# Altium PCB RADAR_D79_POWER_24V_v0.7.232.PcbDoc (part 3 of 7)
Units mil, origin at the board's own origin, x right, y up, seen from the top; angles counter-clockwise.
Board outline 3110.24 x 3110.24 mil, 8 copper layers (Top Layer, GND1, SIG1, PWR1, PWR2, SIG2, GND2, Bottom Layer), stack 55.2 mil thick; 304 components, 269 nets, 1408 pads, 1367 vias.
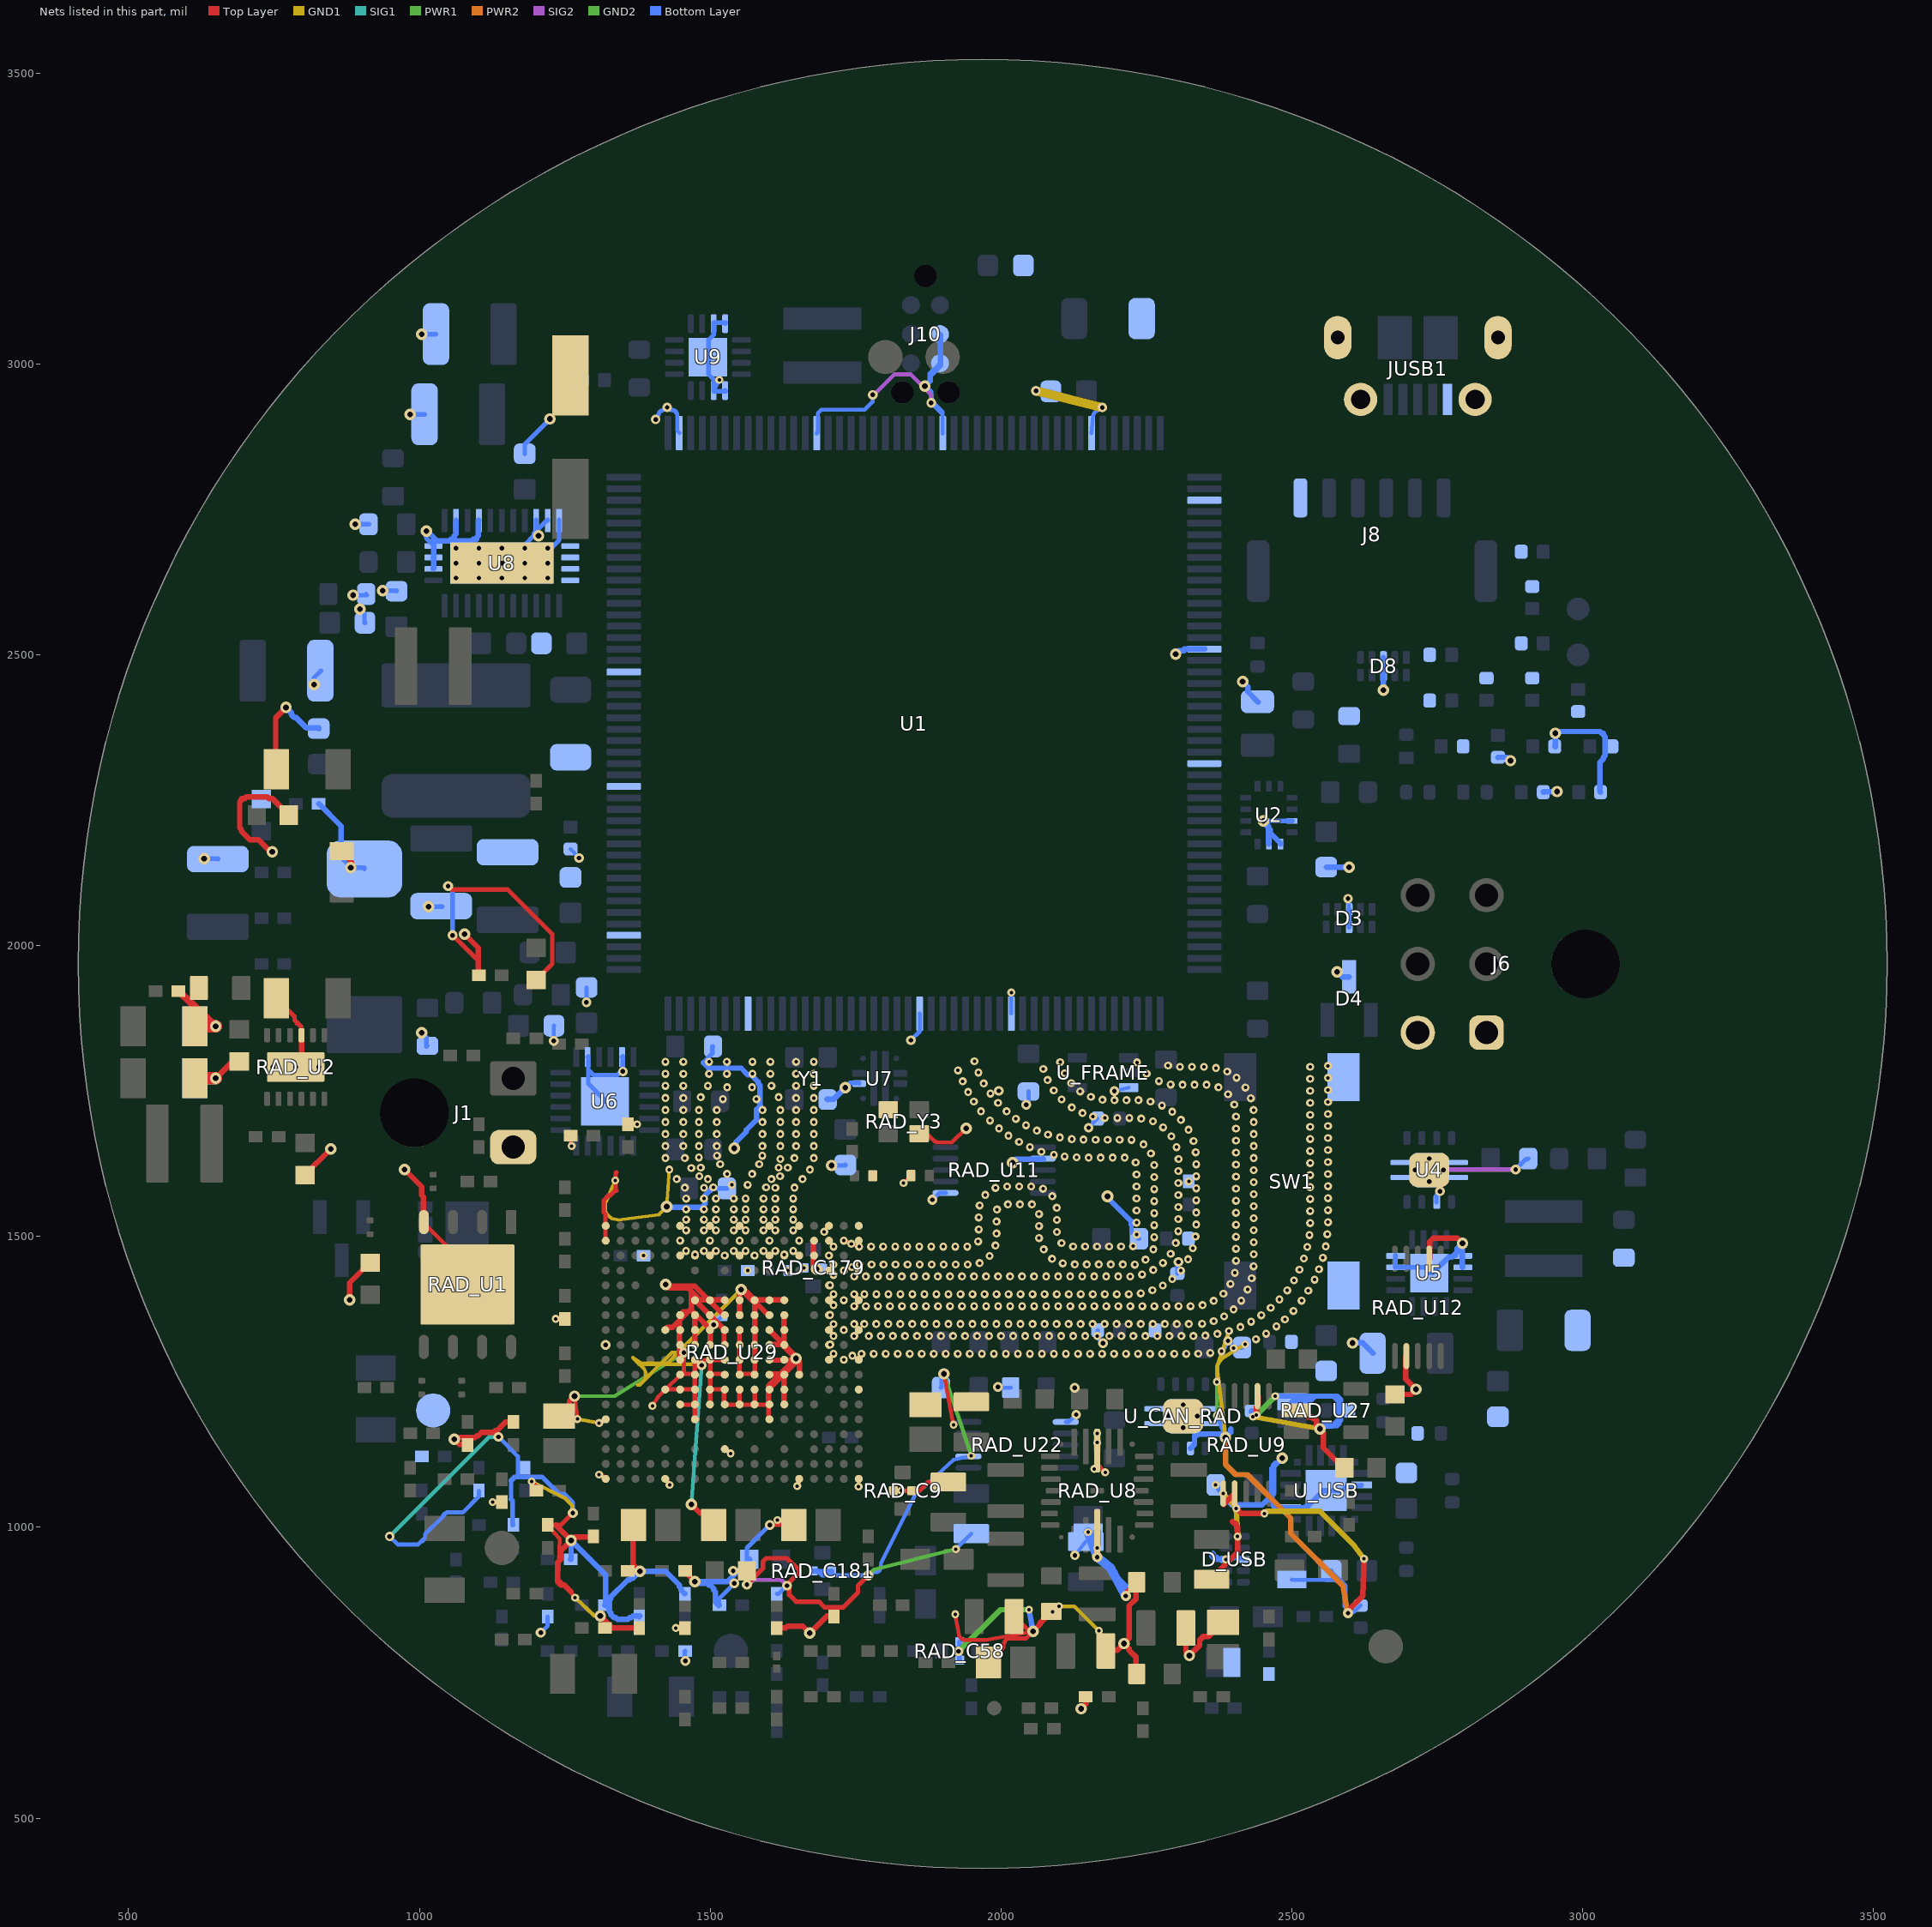
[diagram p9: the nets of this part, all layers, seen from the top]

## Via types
v1: diameter 13.77, hole 5.9, Top Layer to GND1, tented both sides, 393 vias
v2: diameter 16.54, hole 7.87, Top Layer to Bottom Layer, tented both sides, 129 vias
v3: diameter 19.68, hole 9.84, Top Layer to Bottom Layer, tented both sides, 126 vias
v4: diameter 13.77/13.77 (per signal layer), hole 5.9, Top Layer to GND1, tented both sides, 120 vias
v5: diameter 13.77, hole 5.9, Top Layer to GND1, tented top, 104 vias
v6: diameter 13.78, hole 5.91, Top Layer to GND1, tented both sides, 75 vias
v7: diameter 19.68, hole 9.84, Top Layer to Bottom Layer, 74 vias
v8: diameter 17.32, hole 7.87, Top Layer to Bottom Layer, tented both sides, 71 vias
v9: diameter 13.78, hole 5.91, GND2 to Bottom Layer, tented both sides, 64 vias
v10: diameter 13.78, hole 5.91, Top Layer to GND1, tented bottom, 39 vias
v11: diameter 13.78, hole 5.91, GND2 to Bottom Layer, tented top, 38 vias
v12: diameter 13.78, hole 5.91, Top Layer to GND1, 26 vias
v13: diameter 16.54, hole 7.87, GND2 to Bottom Layer, tented both sides, 22 vias
v14: diameter 16.54, hole 7.87, Top Layer to Bottom Layer, 19 vias
v15: diameter 22.05, hole 11.81, Top Layer to Bottom Layer, tented both sides, 17 vias
v16: diameter 13.78, hole 5.91, GND2 to Bottom Layer, 9 vias
v17: diameter 18.11, hole 9.06, Top Layer to Bottom Layer, 7 vias
v18: diameter 22.83, hole 11.81, Top Layer to Bottom Layer, 6 vias
v19: diameter 22.05, hole 11.81, Top Layer to Bottom Layer, 6 vias
v20: diameter 22.83, hole 11.81, Top Layer to Bottom Layer, tented both sides, 5 vias
v21: diameter 19.68, hole 7.87, Top Layer to Bottom Layer, 3 vias
v22: diameter 17.32, hole 8.66, Top Layer to Bottom Layer, 3 vias
v23: diameter 20.47, hole 9.84, Top Layer to Bottom Layer, 3 vias
v24: diameter 17.72, hole 9.84, Top Layer to Bottom Layer, tented both sides, 2 vias
v25: diameter 22.05, hole 11.02, Top Layer to Bottom Layer, 2 vias
v26: diameter 19.68, hole 11.81, Top Layer to Bottom Layer, 2 vias
v27: diameter 18, hole 9.84, Top Layer to Bottom Layer, tented both sides, 1 vias
v28: diameter 18.11, hole 9.06, Top Layer to Bottom Layer, tented both sides, 1 vias

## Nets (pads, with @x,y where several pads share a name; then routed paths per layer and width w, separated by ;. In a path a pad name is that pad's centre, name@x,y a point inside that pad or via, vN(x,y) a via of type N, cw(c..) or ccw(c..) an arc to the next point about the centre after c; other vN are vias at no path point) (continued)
GND: C1.2 C2.2 C3.2 C4.2 C6D.2 C6I.2 C7D.2 C10.2 C11.2 C12.2 C13.2 C14.2 C15.2 C20.2 C21.2 C22.2 C40.2 C90.2 C91.2 C92.2 C93.2 C100.2 C101.2 C102.2 C103.2 C104.2 C105.2 C106.2 C107.2 C108.2 C109.2 C110.2 C111.2 C112.2 C113.2 C114.2 C115.2 C800.2 C801.2 C802.2 C803.2 C804.2 C806.2 C807.2 C808.2 C809.2 C_CAN_RAD.2 C_FRAME.2 C_USB_1U.2 C_USB_4U7.2 C_USB_100N.2 D1.2 D3.3 D3.8 D4.3 D8.3 D8.8 D_USB.3 D_USB.8 J1.2 J6.1 J6.4 J8.6 J10.3 J10.5 JUSB1.5 JUSB1.6 JUSB1.9 JUSB1.10 JUSB1.11 R1.2 R2.2 R10.2 R41.2 R42.2 R63.2 R73.2 R801.2 R802.2 R805.2 R_CAN_SHDN.2 R_CAN_STB.2 R_FRAME_PD.2 R_USB_CTS.1 R_USB_VBUS_L.2 RAD_C1.1 RAD_C2.1 RAD_C5.1 RAD_C6.1 RAD_C8.1 RAD_C9.2 RAD_C10.2 RAD_C15.2 RAD_C22.1 RAD_C23.2 RAD_C25.2 RAD_C26.2 RAD_C29.2 RAD_C31.2 RAD_C58.2 RAD_C60.2 RAD_C92.1 RAD_C96.1 RAD_C99.2 RAD_C100.2 RAD_C101.2 RAD_C102.2 RAD_C103.2 RAD_C104.2 RAD_C105.1 RAD_C106.2 RAD_C107.1 RAD_C108.2 RAD_C110.2 RAD_C111.1 RAD_C112.2 RAD_C113.1 RAD_C114.2 RAD_C115.1 RAD_C116.2 RAD_C117.1 RAD_C118.1 RAD_C119.2 RAD_C125.2 RAD_C126.2 RAD_C129.2 RAD_C130.2 RAD_C132.2 RAD_C134.2 RAD_C137.1 RAD_C138.1 RAD_C139.1 RAD_C140.1 RAD_C141.1 RAD_C142.1 RAD_C143.2 RAD_C144.1 RAD_C145.2 RAD_C146.1 RAD_C149.1 RAD_C150.1 RAD_C153.1 RAD_C163.1 RAD_C164.1 RAD_C165.1 RAD_C168.1 RAD_C170.1 RAD_C172.1 RAD_C173.1 RAD_C174.1 RAD_C175.1 RAD_C176.1 RAD_C177.1 RAD_C179.2 RAD_C180.2 RAD_C181.2 RAD_C195.2 RAD_C199.2 RAD_C200.2 RAD_C201.2 RAD_C202.2 RAD_NT1.1 RAD_NT2.2 RAD_NT3.2 RAD_NT4.2 RAD_R1.2 RAD_R2.1 RAD_R292.1 RAD_R302.1 RAD_R307.1 RAD_R313.1 RAD_U1.4 RAD_U1.9 RAD_U2.9 RAD_U2.13 RAD_U8.12 RAD_U8.26 RAD_U9.1 RAD_U9.2 RAD_U9.7 RAD_U11.1 RAD_U11.7 RAD_U12.2 RAD_U12.7 RAD_U22.1 RAD_U22.7 RAD_U27.2 RAD_U29.A1 RAD_U29.A2 RAD_U29.A4 RAD_U29.A6 RAD_U29.A8 RAD_U29.A10 RAD_U29.A12 RAD_U29.A18 RAD_U29.B2 RAD_U29.B4 RAD_U29.B6 RAD_U29.B8 RAD_U29.B10 RAD_U29.C1 RAD_U29.C2 RAD_U29.C3 RAD_U29.C4 RAD_U29.C5 RAD_U29.C6 RAD_U29.C7 RAD_U29.C8 RAD_U29.C9 RAD_U29.C10 RAD_U29.D2 RAD_U29.D3 RAD_U29.E1 RAD_U29.E2 RAD_U29.E3 RAD_U29.E11 RAD_U29.E18 RAD_U29.F3 RAD_U29.F6 RAD_U29.F7 RAD_U29.F8 RAD_U29.F9 RAD_U29.F10 RAD_U29.F11 RAD_U29.F12 RAD_U29.F13 RAD_U29.G1 RAD_U29.G2 RAD_U29.G3 RAD_U29.G6 RAD_U29.G7 RAD_U29.G8 RAD_U29.G9 RAD_U29.G10 RAD_U29.G11 RAD_U29.G12 RAD_U29.G13 RAD_U29.G14 RAD_U29.H3 RAD_U29.H6 RAD_U29.H7 RAD_U29.H8 RAD_U29.H9 RAD_U29.H10 RAD_U29.H11 RAD_U29.H12 RAD_U29.H13 RAD_U29.J1 RAD_U29.J2 RAD_U29.J3 RAD_U29.J6 RAD_U29.J7 RAD_U29.J8 RAD_U29.J9 RAD_U29.J10 RAD_U29.J11 RAD_U29.J12 RAD_U29.J13 RAD_U29.K3 RAD_U29.K6 RAD_U29.K7 RAD_U29.K8 RAD_U29.K9 RAD_U29.K10 RAD_U29.K11 RAD_U29.K12 RAD_U29.K13 RAD_U29.K16 RAD_U29.L1 RAD_U29.L2 RAD_U29.L3 RAD_U29.L6 RAD_U29.L7 RAD_U29.L8 RAD_U29.L9 RAD_U29.L10 RAD_U29.L11 RAD_U29.L12 RAD_U29.L13 RAD_U29.M3 RAD_U29.M6 RAD_U29.M7 RAD_U29.M8 RAD_U29.M9 RAD_U29.M10 RAD_U29.M11 RAD_U29.M12 RAD_U29.M13 RAD_U29.M14 RAD_U29.N1 RAD_U29.N2 RAD_U29.N3 RAD_U29.N7 RAD_U29.N8 RAD_U29.N9 RAD_U29.N10 RAD_U29.N11 RAD_U29.N12 RAD_U29.N13 RAD_U29.P8 RAD_U29.P12 RAD_U29.P18 RAD_U29.V1 RAD_U29.V2 RAD_U29.V9 RAD_U29.V14 RAD_U29.V18 RAD_Y3.2 RAD_Y3.4 SW1.2 TP_RAD_GND.1 U1.14 U1.22 U1.37 U1.48 U1.61 U1.71 U1.90 U1.102 U1.113 U1.126 U1.135 U1.148 U1.158 U2.6 U2.7 U2.9 U4.2 U4.9 U5.5 U5.6 U5.15 U5.16 U5.17 U6.8 U6.11 U6.25 U7.8 U8.13 U8.14 U8.15 U8.17 U8.19 U8.24 U8.25 U8.26 U8.27 U8.28 U8.29 U8.30 U8.31 U9.5 U9.6 U9.15 U9.16 U9.17 U_CAN_RAD.2 U_CAN_RAD.9 U_FRAME.3 U_USB.3 U_USB.12 U_USB.21 Y1.2 | length 19738.2
  Top Layer w6.3: v6(1309.06,1179.13) 1310.04,1180.12 1313.98,1180.12 1319.88,1186.02 RAD_U29.V14@1320.3,1185.62 ; RAD_U29.P18@1422.67,1083.26 1422.24,1083.66 1428.15,1077.76 1428.15,1074.8 v6(1430.12,1072.83) ; v6(1649.61,1070.87) 1652.56,1073.82 1652.56,1083.66 RAD_U29.E18@1652.98,1083.26 ; v6(1696.01,1507.92) 1696.65,1508.56 1696.65,1510.48 RAD_U29.C1@1704.31,1518.14 ; RAD_U29.C1@1704.16,1518.3 RAD_U29.C1@1704.33,1518.16 ; v6(1754.92,1069.88) 1754.92,1083.66 RAD_U29.A18@1755.34,1083.26 ; v6(1832.28,1591.73) 1845.08,1604.53 RAD_C108.2@1845.21,1604.58
  Top Layer w6.69: RAD_C176.1@1219.49,1003.94 1219.94,1003.45 1241.14,980.32 1240.06,941.83 1239.17,910.43 1248.09,900.59 v6(1267.72,878.94) ; v3(1266.73,1225.39) 1270.56,1194.75 v6(1271.65,1186.02) ; v6(1400.59,1208.66) 1411.42,1225.39 1422.87,1236.59 1423.5,1237.2 1448.75,1261.88 1450.7,1263.78 1454.72,1267.72 v2(1454.72,1300.2) ; v7(1901.57,1263.78) v6(1918.31,1176.18) ; v6(1921.26,850.39) 1928.15,812.01 1934.06,806.1 1974.41,806.1 2028.22,815.95 v3(2055.12,820.87) v6(2088.58,854.33) ; v6(2099.41,864.17) 2099.5,855.45 RAD_C8.1@2099.61,845.28 ; v10(2160.43,1100.39) 2165.36,1100.39 2171.26,1100.39 ; v10(2165.35,964.57) RAD_U8.12@2165.35,994.09 ; v12(2168.31,821.85) RAD_C202.2@2168.6,813.19
  Top Layer w7.09: v6(1125.98,1043.31) RAD_C174.1@1141.73,1043.31 ; v6(1192.91,1078.74) 1200.79,1070.87 RAD_C115.1@1200.79,1062.99 ; v6(1234.25,1358.27) RAD_C2.1@1250,1358.27 ; RAD_C139.1@1259.84,1673.23 1259.84,1657.48 v6(1261.81,1655.51) ; v6(1309.06,1090.55) 1312.99,1090.55 1320.87,1082.68 RAD_U29.V18@1320.3,1083.26 ; v6(1336.71,1596.26) 1337.6,1597.15 1337.6,1609.25 1337.6,1609.55 ; RAD_C142.1@1358.27,1692.91 v6(1374.02,1692.91) ; v6(1440.94,826.77) RAD_C168.1@1456.69,826.77 ; RAD_U29.K16@1525.03,1134.44 1525.39,1134.74 1530.71,1129.43 1532.48,1129.43 v6(1535.14,1126.77) ; v8(1602.36,1003.94) 1615.75,1003.94 RAD_C114.2@1624.31,1003.94 ; v6(1615.75,1012.5) RAD_C114.2@1624.31,1003.94 ; v4(1729.75,1492.7) v4(1742.56,1487.4) 1752.09,1483.89 v1(1756,1482.45) ; RAD_C9.2@1814.96,1062.99 1815.35,1062.99 1815.94,1062.99 v6(1828.74,1062.99) ; RAD_Y3.2@1859.26,1676.68 1860.24,1677.17 1872.05,1677.17 1885.83,1663.39 1887.8,1663.39 1889.76,1661.42 1915.35,1661.42 v3(1939.96,1686.02) ; RAD_C119.2@1978.35,767.72 2003.94,793.31 2003.94,799.21 2005.91,801.18 2005.91,803.15 2011.81,809.06 2043.31,809.06 v3(2055.12,820.87) ; RAD_U8.26@2165.35,1131.89 2165.35,1108.27 2171.26,1102.36 2171.26,1100.39 2173.23,1098.43 2175.2,1098.43 v6(2179.13,1094.49) ; RAD_C114.2@1624.31,1003.94 RAD_C114.2@1643.7,1003.94 1644.09,1003.64 1624.61,1003.64 RAD_C114.2@1624.31,1003.94
  Top Layer w7.87: RAD_C101.2@753.94,1909.45 785.43,1877.95 785.43,1872.05 789.37,1868.11 789.37,1866.14 791.34,1866.14 797.24,1860.24 797.24,1846.46 RAD_U2.9@797.24,1846.06 ; RAD_U1.4@1006.89,1523.62 1083.66,1446.85 1083.66,1417.32 RAD_U1.9@1082.68,1417.32 ; v8(1049.21,2102.36) 1055.12,2096.46 1151.57,2096.46 1228.35,2019.68 1228.35,1968.5 RAD_C126.2@1200.79,1940.94 ; v8(1057.09,2017.72) 1101.38,1973.43 1102.36,1972.44 RAD_R1.2@1102.36,1948.82 ; RAD_C176.1@1219.49,1003.94 RAD_C176.1@1220.47,1003.94 1234.25,1003.94 1243.11,1003.94 v8(1263.78,1024.61) ; RAD_U29.V2@1320.3,1492.7 1319.88,1494.09 RAD_U29.V1@1319.88,1517.72 ; RAD_U29.V1@1320.3,1518.3 RAD_U29.V1@1319.88,1517.72 ; v6@1337.6,1597.15 1337.6,1579.72 ; 1337.6,1609.25 1338.58,1610.24 ; 1338.58,1578.74 1337.6,1579.72 ; RAD_U29.P12@1422.67,1236.8 1423.23,1237.2 1423.5,1237.2 RAD_U29.N12@1446.85,1237.2 ; RAD_U29.N13@1448.26,1211.21 1446.85,1210.63 RAD_U29.M13@1473.43,1210.63 ; RAD_U29.N12@1448.26,1236.8 RAD_U29.N12@1446.85,1237.2 ; RAD_U29.N11@1448.26,1262.39 1446.85,1263.78 1450.7,1263.78 RAD_U29.M11@1473.43,1263.78 ; RAD_U29.M14@1473.85,1185.62 1473.43,1187.01 RAD_U29.M13@1473.43,1210.63 ; RAD_U29.M13@1473.85,1211.21 RAD_U29.M13@1473.43,1210.63 ; RAD_U29.M12@1473.85,1236.8 RAD_U29.M12@1473.43,1237.2 ; RAD_U29.M11@1473.85,1262.39 RAD_U29.M11@1473.43,1263.78 ; RAD_U29.M10@1473.85,1287.98 RAD_U29.M10@1473.43,1287.4 ; RAD_U29.L13@1499.44,1211.21 1500,1210.63 RAD_U29.L12@1500,1237.2 ; RAD_U29.L12@1499.44,1236.8 RAD_U29.L12@1500,1237.2 ; RAD_U29.L11@1499.44,1262.39 RAD_U29.L11@1500,1263.78 ; RAD_U29.L10@1499.44,1287.98 RAD_U29.L10@1500,1287.4 ; RAD_U29.K13@1525.03,1211.21 RAD_U29.K13@1523.62,1210.63 ; RAD_U29.K12@1525.03,1236.8 RAD_U29.K12@1523.62,1237.2 ; RAD_U29.K11@1525.03,1262.39 1523.62,1263.78 RAD_U29.L11@1500,1263.78 ; RAD_U29.K10@1525.03,1287.98 1523.62,1287.4 RAD_U29.L10@1500,1287.4 ; RAD_U29.K9@1525.03,1313.57 1523.62,1313.98 1523.62,1340.55 RAD_U29.K8@1525.03,1339.16 ; v8(1539.37,925.2) RAD_C146.1@1562.99,925.2 ; RAD_U29.J13@1550.62,1211.21 RAD_U29.J13@1550.2,1210.63 ; RAD_U29.J12@1550.62,1236.8 1550.2,1237.2 RAD_U29.J13@1550.2,1210.63 ; RAD_U29.J11@1550.62,1262.39 RAD_U29.J11@1550.2,1263.78 ; RAD_U29.J10@1550.62,1287.98 RAD_U29.J10@1550.2,1287.4 ; RAD_U29.J9@1550.62,1313.57 RAD_U29.J9@1550.2,1313.98 ; RAD_U29.J8@1550.62,1339.16 1550.2,1340.55 RAD_U29.J9@1550.2,1313.98 ; v8(1562.99,901.57) 1590.55,929.13 1590.55,940.94 1596.46,946.85 1631.89,946.85 1653.54,925.2 1653.54,923.23 1635.83,905.51 1635.83,883.86 1647.64,872.05 1687.01,872.05 1696.85,862.2 1728.35,862.2 1753.94,887.8 1753.94,899.61 v8(1771.65,917.32) ; RAD_U29.H13@1576.21,1211.21 RAD_U29.H13@1576.77,1210.63 ; RAD_U29.H12@1576.21,1236.8 1576.77,1237.2 RAD_U29.H13@1576.77,1210.63 ; RAD_U29.H11@1576.21,1262.39 RAD_U29.H11@1576.77,1263.78 ; RAD_U29.H10@1576.77,1287.4 RAD_U29.H11@1576.77,1263.78 ; RAD_U29.G14@1601.8,1185.62 1600.39,1187.01 1600.39,1210.63 RAD_U29.H13@1576.77,1210.63 ; RAD_C9.2@1814.96,1062.99 RAD_C9.2@1815.94,1062.99 ; v6(1828.74,1062.99) RAD_C9.2@1845.47,1062.99 ; RAD_C129.2@2022.64,846.46 2022.64,847.44 2049.21,820.87 v3(2055.12,820.87) ; v8(2214.57,881.89) 2214.57,887.8 2232.28,905.51 RAD_C6.1@2232.28,906.5 ; RAD_U29.V1@1319.88,1517.72 1319.88,1538.39 1316.93,1541.34 1316.93,1562.01 1325.79,1570.87 1328.74,1570.87 1337.6,1579.72 ; RAD_U29.N12@1446.85,1237.2 RAD_U29.M12@1473.43,1237.2 ; RAD_U29.M13@1473.43,1210.63 RAD_U29.M12@1473.43,1237.2 ; RAD_U29.M12@1473.43,1237.2 RAD_U29.M11@1473.43,1263.78 ; RAD_U29.M11@1473.43,1263.78 RAD_U29.M10@1473.43,1287.4 ; RAD_U29.M10@1473.43,1287.4 RAD_U29.L10@1500,1287.4 ; RAD_U29.L12@1500,1237.2 RAD_U29.L11@1500,1263.78 ; RAD_U29.L12@1500,1237.2 RAD_U29.K12@1523.62,1237.2 ; RAD_U29.L11@1500,1263.78 RAD_U29.L10@1500,1287.4 ; RAD_U29.K13@1523.62,1210.63 RAD_U29.J13@1550.2,1210.63 ; RAD_U29.K13@1523.62,1210.63 RAD_U29.K12@1523.62,1237.2 ; RAD_U29.J13@1550.2,1210.63 1576.21,1210.63 RAD_U29.H13@1576.77,1210.63 ; RAD_U29.J11@1550.2,1263.78 RAD_U29.H11@1576.77,1263.78 ; RAD_U29.J11@1550.2,1263.78 RAD_U29.J10@1550.2,1287.4 ; RAD_U29.J10@1550.2,1287.4 1550.2,1313.57 RAD_U29.J9@1550.2,1313.98 ; RAD_C9.2@1845.47,1062.99 RAD_C9.2@1846.46,1062.99 ; RAD_C9.2@1845.47,1062.99 RAD_C9.2@1846.46,1062.99 ; RAD_C9.2@1846.46,1062.99 1860.24,1062.99 1875,1077.76 RAD_C134.2@1909.45,1077.76 ; RAD_C134.2@1909.45,1077.76 1910.43,1077.76 RAD_C134.2@1909.45,1077.76
  Top Layer w9.45: v3(649.61,1772.02) 649.61,1771.65 679.13,1801.18 690.94,1801.18 RAD_C195.2@690.2,1801.01 ; v3(747.05,2161.42) 744.09,2164.37 741.14,2164.37 723.43,2182.09 708.66,2182.09 693.9,2196.85 693.9,2199.8 690.94,2202.76 690.94,2247.05 693.9,2250 693.9,2252.95 699.8,2252.95 702.76,2255.91 738.19,2255.91 741.14,2252.95 747.05,2252.95 RAD_C104.2@775.59,2224.41 RAD_C104.2@776.57,2223.43 ; RAD_C100.2@753.94,2303.15 752.95,2303.15 752.95,2391.73 v3(770.67,2409.45) ; v21(787.4,1791.34) 797.24,1801.18 797.24,1845.47 RAD_U2.9@797.24,1846.06 ; RAD_C10.2@803.56,1605.4 803.15,1606.3 v3(847.44,1650.59) ; RAD_C173.1@866.14,2162.4 865.16,2161.42 882.87,2143.7 882.87,2134.84 v3(881.89,2133.86) ; v3(879.92,1390.75) 879.92,1420.28 914.86,1455.22 915.35,1455.71 RAD_C1.1@915.35,1454.72 ; v3(974.41,1615.16) 1003.94,1585.63 1003.94,1570.87 1006.89,1567.91 1006.89,1523.62 RAD_U1.4@1007.68,1524.67 ; v3(1077.76,2019.68) 1101.38,1996.06 1101.38,1973.43 1101.38,1948.82 RAD_R1.2@1102.36,1948.82 ; RAD_C5.1@1082.68,1141.73 1083.66,1142.72 1068.9,1142.72 v3(1060.04,1151.57) 1062.99,1154.53 1095.47,1154.53 1098.43,1157.48 1101.38,1157.48 1107.28,1163.39 1127.95,1163.39 1130.91,1166.34 1133.86,1166.34 1148.62,1181.1 1160.43,1181.1 RAD_C117.1@1161.42,1181.1 ; 1234.25,1003.94 v3(1260.83,977.36) ; RAD_C112.2@1240.16,1190.94 1240.16,1189.96 1240.65,1190.45 1257.87,1207.68 1257.87,1216.54 v3(1266.73,1225.39) ; 1259.84,889.76 1260.83,888.78 1249.02,900.59 1248.09,900.59 1243.11,900.59 1237.2,906.5 1237.2,938.98 1240.06,941.83 1243.11,944.88 1243.11,959.65 v3(1260.83,977.36) ; RAD_C111.1@1299.21,984.25 1299.21,983.27 1266.73,983.27 v3(1260.83,977.36) ; RAD_R307.1@1318.9,826.77 1319.88,826.77 1319.88,838.58 ; RAD_C165.1@1358.27,925.2 1358.27,924.21 v3(1378.94,924.21) 1367.13,936.02 1367.13,1003.94 RAD_C116.2@1368.11,1003.94 ; RAD_U29.P8@1422.67,1339.16 1423.23,1340.55 1426.18,1343.5 1435.04,1343.5 1446.85,1355.31 ; RAD_U29.N10@1448.26,1287.98 1446.85,1287.4 1446.85,1313.57 RAD_U29.N9@1446.85,1313.98 ; RAD_U29.N9@1448.26,1313.57 RAD_U29.N9@1446.85,1313.98 ; RAD_U29.N8@1448.26,1339.16 RAD_U29.N8@1446.85,1340.55 ; RAD_U29.N7@1448.26,1364.75 1446.85,1364.17 1452.76,1370.08 1461.61,1370.08 ; RAD_C107.1@1456.69,925.2 1455.71,924.21 v3(1473.43,906.5) ; v3(1467.52,1039.37) 1482.28,1024.61 1485.24,1024.61 RAD_C110.2@1505.91,1003.94 ; RAD_U29.M9@1473.85,1313.57 1473.43,1313.98 RAD_U29.M8@1473.43,1340.55 ; RAD_U29.M8@1473.85,1339.16 RAD_U29.M8@1473.43,1340.55 ; RAD_U29.M7@1473.85,1364.75 RAD_U29.M7@1473.43,1364.17 ; RAD_U29.L9@1499.44,1313.57 1500,1313.98 RAD_U29.L8@1500,1340.55 ; RAD_U29.L8@1499.44,1339.16 RAD_U29.L8@1500,1340.55 ; RAD_U29.L6@1499.44,1390.34 RAD_U29.L6@1500,1390.75 ; RAD_U29.K8@1523.62,1340.55 RAD_U29.L7@1500,1364.17 ; RAD_U29.K7@1525.03,1364.75 1523.62,1364.17 1498.45,1389.35 RAD_U29.L6@1497.05,1390.75 ; RAD_U29.K6@1525.03,1390.34 1523.62,1390.75 RAD_U29.L6@1500,1390.75 ; RAD_U29.J7@1550.62,1364.75 1550.2,1364.17 1550.2,1405.51 v3(1553.15,1408.46) ; RAD_U29.H10@1576.21,1287.98 1576.77,1287.4 RAD_U29.H9@1576.77,1313.98 ; RAD_U29.H9@1576.21,1313.57 RAD_U29.H9@1576.77,1313.98 ; RAD_U29.H8@1576.21,1339.16 RAD_U29.H8@1576.77,1340.55 ; RAD_U29.H7@1576.21,1364.75 RAD_U29.H7@1576.77,1364.17 ; RAD_U29.H6@1576.21,1390.34 RAD_U29.H6@1576.77,1390.75 ; RAD_U29.G13@1601.8,1211.21 1600.39,1210.63 RAD_U29.G12@1600.39,1237.2 ; RAD_U29.G12@1601.8,1236.8 RAD_U29.G12@1600.39,1237.2 ; RAD_U29.G11@1601.8,1262.39 1600.39,1263.78 RAD_U29.F11@1621.06,1263.78 ; RAD_U29.G10@1601.8,1287.98 1600.39,1287.4 RAD_U29.F10@1626.97,1287.4 ; RAD_U29.G9@1601.8,1313.57 1600.39,1313.98 1624.02,1313.98 RAD_U29.F9@1626.97,1311.02 ; RAD_U29.G8@1601.8,1339.16 1600.39,1340.55 RAD_U29.F9@1626.97,1313.98 ; RAD_U29.G7@1601.8,1364.75 1600.39,1364.17 RAD_U29.H6@1573.82,1390.75 ; RAD_C163.1@1614.17,826.77 1615.16,826.77 1629.92,826.77 1632.87,829.72 1659.45,829.72 v3(1671.26,817.91) 1700.79,847.44 1712.6,847.44 RAD_C175.1@1712.6,846.46 ; RAD_U29.F13@1627.39,1211.21 1626.97,1210.63 RAD_U29.F12@1626.97,1237.2 ; RAD_U29.F12@1627.39,1236.8 RAD_U29.F12@1626.97,1237.2 ; RAD_U29.F11@1627.39,1262.39 RAD_U29.F11@1626.97,1263.78 ; RAD_U29.F10@1627.39,1287.98 RAD_U29.F10@1626.97,1287.4 ; RAD_U29.F8@1627.39,1339.16 RAD_U29.F8@1626.97,1340.55 ; RAD_U29.F7@1627.39,1364.75 1626.97,1364.17 RAD_U29.F8@1626.97,1340.55 ; RAD_U29.F6@1627.39,1390.34 1626.97,1390.75 RAD_U29.H6@1576.77,1390.75 ; RAD_U29.E11@1652.98,1262.39 1653.54,1263.78 1653.54,1284.45 v3(1647.64,1290.35) ; RAD_U29.D3@1678.57,1467.11 RAD_U29.D3@1677.17,1467.52 ; RAD_U29.D2@1678.57,1492.7 1677.17,1494.09 RAD_U29.D3@1677.17,1467.52 ; v3(1683.07,1443.9) 1677.17,1449.8 1677.17,1467.11 RAD_U29.D3@1677.17,1467.52 ; v3(2055.12,820.87) 2066.93,832.68 2066.93,835.63 RAD_C8.1@2086.61,855.32 ; v3(2137.8,687.99) 2146.65,696.85 2146.65,708.66 RAD_C200.2@2145.67,708.66 ; RAD_C202.2@2180.12,787.4 2179.13,788.39 2199.8,788.39 v3(2211.61,800.2) ; RAD_C153.1@2233.27,748.03 2232.28,747.05 2232.28,776.57 2220.47,788.39 2220.47,791.34 v3(2211.61,800.2) ; RAD_C6.1@2233.27,905.51 2232.28,906.5 2232.28,905.51 2232.28,876.97 2220.47,865.16 2220.47,809.06 v3(2211.61,800.2) ; RAD_C201.2@2317.91,826.77 2317.91,785.43 v3(2323.82,779.53) 2341.54,797.24 2341.54,806.1 2347.44,812.01 2356.3,812.01 2379.92,835.63 2382.87,835.63 RAD_C31.2@2381.89,836.61 ; v12(2381.89,1058.07) RAD_U9.1@2382.87,1057.09 ; RAD_U9.1@2382.87,1039.37 2391.73,1048.23 2400.59,1057.09 RAD_U9.2@2401.57,1058.07 ; 2397.64,1009.84 2400.59,1006.89 2403.54,1006.89 2403.54,1003.94 2406.5,1000.98 v12(2406.5,984.25) 2406.5,956.69 2362.2,912.4 RAD_C143.2@2362.2,910.43 ; v6(2404.53,1032.48) 2413.39,1023.62 v6(2452.76,1023.62) ; 2438.98,1195.87 2438.98,1207.68 2441.93,1210.63 2441.93,1225.39 RAD_U9.7@2440.94,1225.39 ; RAD_U27.2@2507.87,1200.79 2506.89,1201.77 2515.75,1201.77 2527.56,1189.96 2533.46,1189.96 2536.42,1187.01 2539.37,1187.01 2542.32,1184.06 2542.32,1175.2 v3(2548.23,1169.29) 2554.13,1163.39 2554.13,1136.81 2589.57,1101.38 RAD_C149.1@2590.55,1102.36 ; v8@2595.47,855.32 2622.05,881.89 v6(2624.02,945.87) ; RAD_C145.2@2677.17,1228.35 2678.15,1228.35 2704.72,1228.35 v3(2713.58,1237.2) 2695.87,1254.92 2695.87,1293.31 RAD_U12.7@2696.85,1294.29 ; RAD_U12.2@2736.22,1461.61 2737.2,1461.61 2737.2,1491.14 2743.11,1497.05 2784.45,1497.05 v3(2793.31,1488.19) ; 1319.88,838.58 1325.3,833.17 1331.69,826.77 RAD_C96.1@1377.95,826.77 ; 1319.88,838.58 v3(1311.02,847.44) 1319.88,838.58 ; RAD_C96.1@1377.95,826.77 1378.94,826.77 RAD_C96.1@1377.95,826.77 ; RAD_U29.N9@1446.85,1313.98 1446.85,1339.16 RAD_U29.N8@1446.85,1340.55 ; RAD_U29.N8@1446.85,1340.55 1446.85,1355.31 ; 1446.85,1355.32 RAD_U29.N7@1452.27,1360.74 ; 1446.85,1355.31 RAD_U29.N7@1452.27,1360.74 ; RAD_U29.N7@1452.27,1360.74 1461.61,1370.08 ; RAD_U29.N7@1452.27,1360.74 1461.61,1370.08 ; 1461.61,1370.08 1467.52,1375.98 ; 1461.61,1370.08 1467.52,1375.98 ; 1467.52,1375.98 1467.52,1373.03 RAD_U29.M7@1473.43,1367.13 ; 1467.52,1375.98 1467.52,1390.34 1467.52,1396.65 ; 1467.52,1396.65 RAD_U29.M6@1473.43,1390.75 ; 1467.52,1396.65 1467.52,1405.51 ; 1467.52,1405.51 1478.27,1394.76 1482.28,1390.75 RAD_U29.L6@1497.05,1390.75 ; 1467.52,1405.51 1461.61,1411.42 1429.13,1411.42 v3(1423.23,1417.32) 1426.18,1414.37 1473.43,1414.37 RAD_U29.L6@1497.05,1390.75 ; RAD_U29.M8@1473.43,1340.55 RAD_U29.M7@1473.43,1364.17 ; RAD_U29.M7@1473.43,1364.17 1473.43,1364.75 RAD_U29.M7@1473.43,1367.13 ; RAD_U29.M7@1473.43,1367.13 1474.82,1365.73 RAD_U29.L8@1500,1340.55 ; RAD_U29.M6@1473.43,1390.75 RAD_U29.M6@1473.85,1390.34 ; RAD_U29.M6@1473.43,1390.75 RAD_U29.M6@1473.85,1390.34 ; RAD_U29.M6@1473.85,1390.34 RAD_U29.L7@1499.43,1364.74 ; RAD_U29.L6@1497.05,1390.75 1499.44,1390.75 RAD_U29.L6@1500,1390.75 ; RAD_U29.L7@1499.43,1364.74 RAD_U29.L7@1500,1364.17 ; RAD_U29.L7@1499.44,1364.75 RAD_U29.L7@1500,1364.17 ; v3(1553.15,1408.46) 1562.01,1399.61 ; v3(1553.15,1408.46) 1559.06,1408.46 RAD_U29.H6@1576.77,1390.75 ; v3(1553.15,1408.46) RAD_U29.H6@1570.87,1390.75 ; 1562.01,1399.61 RAD_U29.H6@1570.87,1390.75 ; 1562.01,1399.61 1564.96,1399.61 RAD_U29.H6@1573.82,1390.75 ; RAD_U29.H6@1570.87,1390.75 RAD_U29.H6@1573.82,1390.75 ; RAD_U29.H6@1570.87,1390.75 1573.74,1387.87 1576.77,1384.84 1576.77,1364.75 RAD_U29.H7@1576.77,1364.17 ; RAD_U29.H6@1573.82,1390.75 RAD_U29.H6@1576.77,1390.75 ; RAD_U29.H9@1576.77,1313.98 1576.77,1339.16 RAD_U29.H8@1576.77,1340.55 ; RAD_U29.H8@1576.77,1340.55 RAD_U29.H7@1576.77,1364.17 ; RAD_U29.G12@1600.39,1237.2 RAD_U29.F11@1626.97,1263.78 ; RAD_U29.G12@1600.39,1237.2 1600.39,1243.11 RAD_U29.F11@1621.06,1263.78 ; RAD_U29.F11@1621.06,1263.78 1623.53,1266.25 1626.97,1269.68 ; RAD_U29.F12@1626.97,1237.2 1626.97,1262.39 RAD_U29.F11@1626.97,1263.78 ; RAD_U29.F11@1626.97,1263.78 1635.83,1272.64 ; RAD_U29.F11@1626.97,1263.78 1626.97,1269.68 ; RAD_U29.F11@1626.97,1263.78 1635.83,1272.64 ; 1626.97,1269.68 1635.83,1278.54 ; RAD_U29.F10@1626.97,1287.4 1627.39,1287.4 v3@1644.68,1287.4 ; RAD_U29.F9@1626.97,1311.02 1626.97,1313.57 RAD_U29.F9@1626.97,1313.98 ; RAD_U29.F9@1626.97,1311.02 v3@1644.68,1293.31 ; RAD_U29.F9@1626.97,1313.98 1626.97,1339.16 RAD_U29.F8@1626.97,1340.55 ; RAD_U29.F9@1626.97,1313.98 1635.83,1305.12 ; RAD_U29.F9@1626.97,1313.98 RAD_U29.F9@1627.39,1313.57 ; RAD_U29.F9@1626.97,1313.98 RAD_U29.F9@1627.39,1313.57 ; RAD_U29.F9@1627.39,1313.57 1635.83,1305.12 ; 1635.83,1272.64 1644.68,1281.5 v3@1644.68,1287.4 ; 1635.83,1272.64 1635.83,1278.54 ; 1635.83,1278.54 v3@1644.68,1287.4 ; 1635.83,1305.12 1635.83,1302.17 v3@1644.68,1293.31 ; 1635.83,1305.12 1644.68,1296.26 v3@1644.68,1293.31 ; v3@1644.68,1287.4 v3(1647.64,1290.35) ; v3@1644.68,1287.4 v3(1647.64,1290.35) ; v3@1644.68,1293.31 v3(1647.64,1290.35) ; RAD_C8.1@2086.61,855.32 2087.11,855.81 2087.6,856.3 RAD_C8.1@2086.61,855.32 ; RAD_C143.2@2362.2,910.43 2362.2,909.45 RAD_C143.2@2362.2,910.43
  Top Layer w11.81: v8(2165.35,948.82) v10(2165.35,964.57) RAD_U8.12@2165.35,994.09 ; RAD_U8.26@2165.35,1131.89 v12(2165.35,1145.67) v6(2165.35,1161.42)
  Top Layer w12.6: RAD_C22.1@585.65,1921.91 601.62,1906.73 630.96,1878.84 v3(649.61,1861.12)
  Top Layer w21.65: RAD_C29.2@614.12,1772.02 v3(649.61,1772.02) ; RAD_C25.2@614.12,1861.12 v3(649.61,1861.12)
  PWR1 w6.3: v3(1266.73,1225.39) 1335.63,1225.39 v2(1454.72,1300.2)
  PWR2 w9.45: v3(2385.83,1154.53) 2385.83,1108.27 2403.54,1090.55 2423.23,1090.55 2498.03,1015.75 2498.03,989.17 2587.6,899.61 v8@2595.47,855.32
  GND1 w6.3: v6(1336.71,1596.26) 1319.88,1557.09 1319.88,1543.31 1322.83,1537.4 1330.71,1530.51 1342.52,1528.54 1411.42,1537.4 v23(1425.2,1551.18) v4(1429.74,1615) ; 1367.13,1291.34 1386.81,1271.65 1388.78,1265.75 1388.78,1258.86 1385.83,1251.97 ; v2(1454.72,1300.2) 1444.88,1300.2 1434.06,1300.2 1415.35,1281.5 1414.37,1280.51 1385.83,1251.97 ; 1379.92,1246.06 1378.94,1245.08 1375,1245.08 1379.92,1246.06 ; 1379.92,1246.06 1385.83,1251.97
  GND1 w6.69: v6(1192.91,1078.74) 1250,1050.2 1262.8,1037.4 v8(1263.78,1024.61) ; v6(1267.72,878.94) 1301.18,847.44 v3(1311.02,847.44) ; v6(1271.65,1186.02) v6(1309.06,1179.13) ; v2(1485.24,1278.54) 1483.27,1280.51 1414.37,1280.51 1377.95,1280.51 1367.13,1291.34 1381.89,1281.5 1415.35,1281.5 1426.18,1281.5 1444.88,1300.2 v3(1553.15,1408.46) ; v6(2099.41,864.17) 2125.98,864.17 v12(2168.31,821.85) ; v1(2392,1337.51) 2380.09,1302.29 2372.72,1280.49 ; v1(2419.66,1314.71) 2402.57,1304.08 2378.94,1289.37 2372.72,1280.49 ; 2372.05,1267.52 2371.06,1275.59 2372.05,1278.5 ; 2372.05,1267.52 v3(2385.83,1154.53) 2372.05,1263.78 2372.05,1267.52 ; 2372.05,1267.52 2372.05,1278.5 ; 2372.05,1278.5 2372.05,1279.53 2372.72,1280.49 ; 2372.05,1278.5 2372.72,1280.49
  GND1 w7.09: v4(1729.75,1492.7) v4(1742.56,1487.4) v1(1756,1482.45)
  GND1 w9.45: v12(2381.89,1058.07) v6(2404.53,1032.48) v12(2406.5,984.25) ; v12(2433.07,1189.96) v3(2548.23,1169.29) ; v6(2452.76,1023.62) 2456.69,1027.56 2548.23,1027.56 2606.3,969.49 v6(2624.02,945.87)
  GND1 w15.75: v2(2060.04,2953.74) v2(2174.21,2925.2)
  SIG1 w6.69: v3(1467.52,1039.37) v2(1485.24,1278.54)
  SIG1 w7.09: v2(948.82,984.25) 1120.08,1155.51 v2(1135.83,1155.51)
  SIG2 w7.09: v8(1562.99,901.57) 1566.93,901.57 1574.8,909.45 1622.05,909.45 v2(1631.89,899.61) ; v2(1779.53,2946.85) 1781.5,2946.85 1816.93,2982.28 1844.49,2982.28 1879.92,2946.85 v2(1879.92,2933.07)
  SIG2 w7.87: U4.9@2760.83,1614.17 2760.83,1615.16 v8(2884.84,1615.16)
  GND2 w6.69: v8(1771.65,917.32) 1781.5,927.17 v9(1922.24,962.6) ; v7(1901.57,1263.78) v11(1948.82,1123.03) ; v9(2371.06,1191.93) v9(2371.06,1250)
  GND2 w9.45: v13(1926.97,786.91) 1999.02,858.27 v9(2048.23,858.27) ; v16(2369.09,1072.83) v16@2370.08,1071.85 ; v16(2438.98,1192.91) v9(2471.46,1225.39)
  Bottom Layer w6.3: C13.2@1259.84,2166.14 v13(1274.61,2150.59) ; v13(1505.91,1348.43) RAD_C103.2@1519.69,1362.21 ; U9.6@1505.91,2953.49 1506.21,2954.08 v9(1515.75,2972.44) ; U1.14@2017.72,1882.87 v9(2017.72,1919.29) ; v13(2126.97,951.77) RAD_C132.2@2145.67,975.39 ; v13(2150.59,1687.01) C_FRAME.2@2166.14,1702.76 ; v13(2194.88,1750) U_FRAME.3@2219.49,1755.91 ; v13(2596.46,2080.71) D3.8@2598.43,2062.4
  Bottom Layer w6.69: v8(1771.65,917.32) 1782.93,923.23 1792.32,928.15 1794.29,939.96 1851.38,1054.13 1918.31,1116.14 ; v9(1922.24,962.6) RAD_C130.2@1948.82,989.17 ; RAD_U22.7@1943.9,1122.05 1918.37,1116.16 ; v11(1948.82,1123.03) 1943.92,1121.93 1918.37,1116.16 ; v9(2371.06,1191.93) 2374.24,1183.87 v3(2385.83,1154.53) ; v9(2371.06,1250) 2371.06,1275.59 v13(2390.16,1320.47) ; 1918.31,1116.14 1918.37,1116.16 ; 1918.31,1116.14 1918.37,1116.16
  Bottom Layer w7.09: v2(948.82,984.25) 962.6,970.47 998.03,970.47 1003.94,976.38 1005.91,976.38 1005.91,978.35 1009.84,982.28 1009.84,988.19 1041.34,1019.68 1041.34,1021.65 1043.31,1021.65 1043.31,1023.62 1045.28,1023.62 1047.24,1025.59 1074.8,1025.59 1102.36,1053.15 RAD_C177.1@1102.36,1062.99 ; v2(1135.83,1155.51) 1169.29,1122.05 1169.29,1090.55 1165.35,1086.61 1157.48,1078.74 1157.48,1048.23 ; v8(1208.66,818.9) 1220.47,830.71 RAD_R302.1@1220.47,846.46 ; v13(1230.91,1836.12) 1230.91,1861.71 C6I.2@1231.3,1862.2 ; v13(1287.2,1902.66) 1287.2,1928.25 C6D.2@1287.4,1928.15 ; v13@1349.41,1786.42 1349.9,1786.22 v13(1349.9,1783.66) ; v13(1406.2,2904.53) 1410.04,2908.37 1410.04,2910.93 1411.32,2912.2 1411.32,2914.76 1412.6,2916.04 1412.6,2917.32 1413.88,2918.6 1415.16,2918.6 1416.44,2919.88 1417.72,2919.88 1419,2921.16 v13@1431.2,2921.16 ; v13(1425.89,2925.39) 1426.97,2924.31 1428.05,2924.31 v13@1431.2,2921.16 ; 1442.37,2916.09 1442.23,2915.84 ; U1.90@1446.85,2880.91 1447.15,2881.5 1443.31,2885.33 1443.31,2914.76 1442.23,2915.84 ; RAD_C105.1@1456.69,787.4 1456.1,786.91 1456.1,771.56 v13(1457.38,770.28) ; RAD_C170.1@1614.17,885.83 1618.11,885.83 v2(1631.89,899.61) ; U1.102@1683.07,2880.91 1683.07,2879.92 1685.04,2881.89 1685.04,2915.35 1690.94,2921.26 1765.75,2921.26 1779.53,2935.04 v2(1779.53,2946.85) ; v8(1771.65,917.32) 1777.56,923.23 1782.93,923.23 1787.4,923.23 1789.37,925.2 1791.34,925.2 ; v13(1845.08,1837.4) 1860.43,1852.76 1860.43,1883.46 U1.22@1860.24,1882.87 ; v3(1869.09,2961.61) 1870.08,2962.6 1879.92,2952.76 1879.92,2940.94 1881.89,2938.98 1881.89,2935.04 1899.61,2917.32 1899.61,2913.39 ; v2(1879.92,2933.07) 1899.61,2913.39 ; v8(1881.89,1562.99) 1893.7,1574.8 RAD_U11.1@1904.53,1574.8 ; v13(1926.97,786.91) 1928.15,785.73 1928.25,785.63 1928.25,770.77 1928.25,770.28 RAD_C58.2@1928.15,770.67 ; v13(1994.78,1241.14) 1996.06,1239.86 2016.54,1239.86 RAD_C144.1@2016.73,1240.16 ; v8(2043.31,1726.38) 2047.24,1730.32 R_FRAME_PD.2@2047.24,1749.02 ; v2(2060.04,2953.74) C11.2@2085.63,2952.76 ; RAD_U22.1@2111.22,1181.1 2111.22,1181 2116.34,1181 v13(2129.13,1193.8) ; U1.126@2155.51,2880.91 2158.46,2911.42 2160.43,2916.34 v2(2174.21,2925.2) ; C112.2@2166.14,1338.58 2166.24,1338.39 2166.24,1325.59 v13(2175.2,1316.63) ; C107.2@2303.15,1436.22 2302.85,1436.71 2302.85,1454.04 v13(2305.02,1456.2) ; 2364.17,956.69 2366.14,954.72 2366.14,952.76 2370.08,948.82 2372.05,948.82 2374.02,946.85 2415.35,946.85 2417.32,944.88 D_USB.3@2416.73,944.88 ; v13(2390.16,1320.47) 2401.67,1308.96 2414.47,1308.96 R_CAN_SHDN.2@2414.37,1309.06 ; RAD_NT1.1@2500,910.2 2500,909.45 2574.8,909.45 2576.77,907.48 2578.74,907.48 2590.55,895.67 2590.55,864.17 2592.52,862.2 ; C_USB_4U7.2@2567.91,925.2 2566.93,925.2 2592.52,899.61 2592.52,862.2 ; C_USB_100N.2@2618.11,865.35 2618.11,866.14 2606.3,854.33 2598.43,854.33 v8(2596.46,852.36) v8@2594.49,854.33 ; U4.2@2749.02,1559.06 2748.43,1558.46 2748.43,1571.26 v13(2754.82,1577.66) ; 1157.48,1048.23 1157.48,1047.24 1157.48,1048.23 ; v13@1431.2,2921.16 1435.63,2921.16 1436.81,2919.98 ; v13@1431.2,2921.16 1431.3,2921.06 1434.55,2921.06 1435.63,2919.98 1436.81,2919.98 ; 1436.81,2919.98 1437.8,2919.98 1437.89,2919.88 ; 1436.81,2919.98 1436.91,2919.88 1437.89,2919.88 ; 1437.89,2919.88 1442.13,2915.65 1442.23,2915.84 ; 1437.89,2919.88 1438.19,2919.88 1439.47,2918.6 1440.75,2918.6 1440.75,2917.32 1442.23,2915.84 ; U1.113@1899.61,2880.91 1899.61,2879.92 U1.113@1899.61,2880.91 ; U1.113@1899.61,2880.91 1899.61,2913.39 ; RAD_U11.1@1904.53,1574.8 1905.51,1574.8 RAD_U11.1@1904.53,1574.8 ; R_FRAME_PD.2@2047.24,1749.02 2047.24,1750 R_FRAME_PD.2@2047.24,1749.02 ; 2592.52,862.2 2592.52,856.3 v8@2594.49,854.33 ; 2592.52,862.2 2594.49,860.24 v8@2594.49,854.33
  Bottom Layer w7.87: v7(629.92,2149.61) 653.54,2149.61 C809.2@653.54,2148.62 ; v7(818.9,2448.82) 818.9,2460.63 830.22,2471.95 830.71,2472.44 C808.2@829.72,2472.44 ; v3(881.89,2133.86) 905.51,2133.86 D1.2@905.51,2131.89 ; v7(885.83,2602.36) 909.45,2602.36 R802.2@908.46,2604.33 ; v7(889.76,2724.41) R801.2@912.4,2724.41 R801.2@913.39,2724.41 ; v7(897.64,2578.74) 905.51,2570.87 905.51,2555.12 C804.2@906.5,2555.12 ; v3(937.01,2610.24) 960.63,2610.24 C803.2@960.63,2609.25 ; v7(984.25,2913.39) C800.2@1008.86,2913.39 ; v7(1003.94,1850.39) 1011.81,1842.52 1011.81,1826.77 R63.2@1013.78,1827.76 ; v7(1003.94,3051.18) C801.2@1028.54,3051.18 ; v7(1011.81,2712.6) 1011.81,2700.79 1023.62,2688.98 U8.15@1024.11,2687.01 ; v7(1015.75,2066.93) 1039.37,2066.93 C806.2@1037.4,2067.91 ; v8(1049.21,2102.36) 1057.09,2094.49 v8(1057.09,2017.72) ; 1157.48,1048.23 1160.43,1045.28 1160.43,1003.94 RAD_C92.1@1161.42,1003.94 ; 1157.48,1078.74 1157.48,1080.71 1163.39,1086.61 1165.35,1086.61 1210.63,1086.61 1240.16,1057.09 1249.02,1057.09 1263.78,1042.32 v8(1263.78,1024.61) ; U8.31@1181.1,2688.98 1196.85,2704.72 1196.85,2708.66 U8.24@1200.79,2712.6 ; C802.2@1181.1,2845.47 1181.1,2862.2 v7(1224.41,2905.51) ; U8.24@1200.79,2732.28 U8.24@1200.79,2730.81 U8.24@1200.79,2712.6 ; v3(1204.72,2704.72) 1200.79,2708.66 U8.24@1200.79,2712.6 ; U8.25@1220.47,2730.81 1220.47,2732.28 1209.89,2721.7 U8.24@1200.79,2712.6 ; U8.31@1224.41,2681.1 1240.16,2696.85 U8.26@1240.16,2730.81 U8.26@1240.16,2732.28 ; U6.8@1289.37,1808.56 1290.35,1810.04 1290.35,1808.56 1290.35,1786.42 ; U6.25@1318.9,1732.28 1319.88,1733.27 1290.35,1762.8 1290.35,1786.42 ; U6.11@1348.43,1808.56 1349.41,1810.04 1349.41,1786.42 1340.55,1777.56 1299.21,1777.56 1290.35,1786.42 ; 1488.19,1799.21 1503.94,1814.96 1503.94,1826.77 R1.2@1504.92,1826.77 ; U9.17@1496.06,3011.81 U9.17@1497.05,3011.81 ; 1500,1578.74 1503.94,1582.68 R805.2@1528.54,1582.68 ; RAD_C164.1@1514.76,865.16 1514.76,876.97 v8(1541.34,903.54) ; U9.5@1525.59,2954.23 1526.57,2952.76 U9.6@1505.91,2952.76 ; U9.16@1525.59,3069.39 1526.57,3070.87 U9.15@1505.91,3070.87 ; v8(1539.37,925.2) 1547.24,925.2 RAD_C137.1@1562.99,940.94 ; v8(1562.99,901.57) 1562.99,939.96 RAD_C137.1@1562.99,940.94 ; RAD_C137.1@1566.93,944.88 RAD_C137.1@1562.99,940.94 ; v8(1602.36,1003.94) 1562.99,964.57 RAD_C137.1@1562.99,940.94 ; RAD_C181.2@1708.66,925.2 1709.65,924.21 1686.02,924.21 ; v7(1708.66,1622.05) 1732.28,1622.05 C7D.2@1732.28,1623.03 ; v3(1732.28,1755.91) 1740.16,1763.78 1755.91,1763.78 U7.8@1755.91,1762.8 ; v8(1771.65,917.32) 1692.91,917.32 1686.02,924.21 ; R73.2@1896.65,1240.16 1897.64,1240.16 1897.64,1259.84 v7(1901.57,1263.78) ; RAD_C58.2@1929.13,771.65 1928.25,770.77 1928.15,770.67 1928.15,785.73 1928.15,803.15 RAD_C58.2@1929.13,803.15 ; v8(2165.35,948.82) 2193.31,920.87 2214.57,899.61 v8(2214.57,881.89) ; 2224.41,1519.68 2224.41,1507.87 2236.22,1496.06 R2.2@2237.2,1496.06 ; v3(2450.79,2214.57) U2.9@2500.49,2214.57 ; U_USB.21@2560.04,1062.99 2586.61,1062.99 2595.47,1071.85 2619.09,1071.85 U_USB.3@2620.08,1072.83 ; D3.3@2598.43,2032.09 2598.43,2031.5 D3.3@2598.43,2032.09 2598.43,2061.02 D3.8@2598.43,2062.4 ; U5.16@2678.64,1466.54 2678.15,1467.52 U5.15@2678.15,1446.85 ; U5.17@2736.22,1437.01 2737.2,1437.99 2728.35,1446.85 U5.15@2678.64,1446.85 ; v8(2884.84,1615.16) 2902.56,1632.87 2905.51,1632.87 R41.2@2906.5,1633.86 ; U9.17@1497.05,3011.81 1497.05,2982.28 1505.91,2973.43 U9.6@1505.91,2954.23 ; U9.17@1497.05,3011.81 1497.05,3041.34 1505.91,3050.2 U9.15@1505.91,3069.39 ; U9.6@1505.91,2952.76 U9.6@1505.91,2953.49 ; U9.6@1505.91,2952.76 U9.6@1505.91,2953.49 ; U9.6@1505.91,2953.49 U9.6@1505.91,2954.23 ; U9.6@1505.91,2953.49 U9.6@1505.91,2954.23 ; U9.15@1505.91,3069.39 U9.15@1505.91,3070.87 ; U9.15@1505.91,3069.39 U9.15@1505.91,3070.87 ; 1686.02,924.21 1677.17,924.21 RAD_C181.2@1677.17,925.2 1685.04,925.2 1686.02,924.21 ; U2.9@2500.49,2214.57 2500.98,2214.57 U2.9@2500.49,2214.57 ; U5.15@2678.15,1446.85 U5.15@2678.64,1446.85 ; U5.15@2678.15,1446.85 U5.15@2678.64,1446.85
  Bottom Layer w9.06: v23(1425.2,1551.18) 1426.18,1550.2 1485.24,1550.2 1491.14,1556.1 1491.14,1570.87 1500,1579.72 1500,1578.74 ; 1488.19,1799.21 1488.19,1798.23 1497.05,1789.37 1553.15,1789.37 1564.96,1777.56 1570.87,1777.56 1582.68,1765.75 1582.68,1762.8 1585.63,1759.84 1585.63,1724.41 1579.72,1718.5 1579.72,1700.79 1562.01,1683.07 1562.01,1680.12 1544.29,1662.4 1544.29,1653.54 1541.34,1650.59 v23(1541.34,1651.57) ; v23(2183.07,1568.9) 2182.09,1567.91 2223.43,1526.57 2223.43,1520.67 2224.41,1519.68
  Bottom Layer w9.45: v3(770.67,2409.45) 779.53,2400.59 779.53,2397.64 785.43,2391.73 788.39,2391.73 806.1,2374.02 826.77,2374.02 C93.2@826.77,2373.03 ; RAD_R2.1@826.77,2244.09 865.16,2205.71 865.16,2152.56 882.87,2134.84 v3(881.89,2133.86) ; v7(1011.81,2712.6) v7@1012.8,2713.58 ; U8.13@1024.11,2647.64 1024.61,2648.62 U8.14@1024.61,2666.34 ; U8.14@1024.11,2667.32 U8.14@1024.61,2666.34 ; U8.19@1102.36,2730.81 1101.38,2731.3 1101.38,2704.72 1098.43,2701.77 1098.43,2698.82 1092.52,2698.82 1089.57,2695.87 1051.18,2695.87 ; RAD_C138.1@1259.84,944.88 1260.83,944.88 v3(1260.83,977.36) 1319.88,918.31 1319.88,865.16 RAD_C140.1@1318.9,866.14 ; RAD_C113.1@1377.95,846.46 1378.94,847.44 1367.13,847.44 1364.17,844.49 1361.22,844.49 1358.27,841.54 1340.55,841.54 1337.6,844.49 1334.65,844.49 1328.74,850.39 1328.74,853.35 1325.79,856.3 1325.79,874.02 1328.74,876.97 1328.74,879.92 1358.27,909.45 1361.22,909.45 1364.17,912.4 1367.13,912.4 v3(1378.94,924.21) 1423.23,924.21 1446.85,900.59 1446.85,897.64 1449.8,894.68 1449.8,891.73 1455.71,885.83 RAD_C172.1@1456.69,885.83 ; RAD_C164.1@1515.75,866.14 1514.76,865.16 1508.86,871.06 1508.86,888.78 1505.91,891.73 1505.91,894.68 1500,900.59 1497.05,900.59 1494.09,903.54 1476.38,903.54 v3(1473.43,906.5) 1529.53,906.5 1562.99,939.96 1567.91,944.88 RAD_C137.1@1566.93,944.88 ; Y1.2@1701.77,1735.24 1700.79,1736.22 1712.6,1736.22 1733.27,1756.89 v3(1732.28,1755.91) ; v3@1870.08,2962.6 1877.95,2970.47 1877.95,2979.33 ; J10.5@1895.08,3001.18 J10.5@1895.67,3000 ; J10.3@1895.08,3051.18 1895.67,3050.2 J10.5@1895.67,3000 ; v3(2019.68,1626.97) 2025.59,1632.87 2072.83,1632.87 RAD_U11.7@2071.85,1633.86 ; v9(2048.23,858.27) v3(2055.12,820.87) ; v3(2300.2,2500.98) 2306.1,2506.89 2314.96,2506.89 2314.96,2509.84 2350.39,2509.84 U1.148@2349.41,2509.84 ; U_CAN_RAD.2@2325.79,1135.83 2326.77,1136.81 2332.68,1142.72 2332.68,1157.48 2335.63,1157.48 2338.58,1160.43 2379.92,1160.43 v3(2385.83,1154.53) 2394.68,1163.39 2394.68,1169.29 ; 2362.2,950.79 2368.11,944.88 2385.83,944.88 v16(2386.42,944.88) ; R_CAN_STB.2@2368.11,1071.85 v16(2369.09,1072.83) ; R_CAN_STB.2@2370.08,1071.85 2385.83,1049.21 2396.65,1038.39 2448.82,1038.39 2468.5,1058.07 2468.5,1104.33 ; v3(2415.35,2453.74) 2424.21,2444.88 2424.21,2436.02 2441.93,2418.31 C12.2@2440.94,2419.29 ; C_CAN_RAD.2@2430.12,1198.82 C_CAN_RAD.2@2431.1,1200 ; U2.6@2460.63,2174.7 2459.65,2176.18 2459.65,2202.76 ; v9(2471.46,1225.39) 2571.85,1225.39 2580.71,1216.54 2580.71,1185.04 2569.88,1174.21 2553.15,1174.21 v3(2548.23,1169.29) 2554.13,1175.2 2577.76,1175.2 2580.71,1178.15 2580.71,1181.1 2583.66,1184.06 2583.66,1219.49 2577.76,1225.39 2539.37,1225.39 2530.51,1216.54 2500.98,1216.54 RAD_NT2.2@2500,1215.79 ; U2.7@2480.31,2174.7 2480.32,2176.18 2462.6,2193.9 2462.6,2199.8 2459.65,2202.76 ; C21.2@2559.06,2134.84 2560.04,2134.84 v3(2598.43,2134.84) ; v3(2577.76,1954.72) 2586.61,1945.87 2598.43,1945.87 D4.3@2598.43,1946.36 ; v3(2604.33,1316.93) 2622.05,1316.93 2639.27,1299.7 2639.76,1299.21 C1.2@2638.78,1299.21 ; v3(2657.48,2438.98) D8.8@2657.48,2465.16 ; D8.3@2657.48,2495.47 2657.48,2495.08 D8.8@2657.48,2465.55 ; U5.17@2737.2,1437.99 2743.11,1437.99 2769.68,1464.57 2775.59,1464.57 2778.54,1467.52 2781.5,1467.52 2781.5,1470.47 2784.45,1473.43 2784.45,1479.33 v3(2793.31,1488.19) 2793.31,1446.85 U5.6@2793.8,1446.85 ; C106.2@2854.33,2323.62 2855.32,2323.82 2870.08,2323.82 v3(2875.98,2317.91) ; C109.2@2932.28,2263.78 2932.09,2264.76 v3(2955.71,2264.76) ; C110.2@2951.97,2342.52 2952.76,2341.54 v3(2952.76,2365.16) 2955.71,2368.11 3029.53,2368.11 3032.48,2365.16 3035.43,2365.16 3035.43,2362.2 3038.39,2359.25 3038.39,2326.77 3035.43,2323.82 3035.43,2320.87 3029.53,2314.96 3029.53,2264.76 C20.2@3030.71,2263.78 ; v7@1012.8,2713.58 1024.61,2701.77 ; v7@1012.8,2713.58 1024.61,2701.77 ; U8.14@1024.61,2666.34 1024.61,2667.32 1024.61,2687.01 1024.61,2701.77 ; 1024.61,2701.77 1030.51,2695.87 1051.18,2695.87 ; 1051.18,2695.87 1054.13,2698.82 1057.09,2698.82 1060.04,2701.77 1060.04,2704.72 1062.99,2707.68 U8.17@1062.99,2730.81 ; U8.17@1062.99,2730.81 1062.99,2731.3 U8.17@1062.99,2730.81 ; 1877.95,2979.33 1877.95,2982.28 J10.5@1895.67,3000 ; 1877.95,2979.33 1895.67,2997.05 J10.5@1895.67,3000 ; 2459.65,2202.76 2450.79,2211.61 v3(2450.79,2214.57) 2459.65,2205.71 2459.65,2202.76 ; 2468.5,1104.33 v3(2483.27,1119.09) 2474.41,1110.24 2471.46,1110.24 2468.5,1107.28 2468.5,1104.33 ; 2468.5,1104.33 2465.55,1101.38 2465.55,1045.28 2468.5,1042.32 2468.5,1036.42 2471.46,1036.42 2474.41,1033.46 2521.65,1033.46 2524.61,1036.42 2527.56,1036.42 2554.13,1062.99 U_USB.21@2559.06,1062.99 ; U_USB.21@2559.06,1062.99 2560.04,1062.99 U_USB.21@2559.06,1062.99 ; D8.8@2657.48,2465.16 D8.8@2657.48,2465.55 ; D8.8@2657.48,2465.16 D8.8@2657.48,2465.55
  Bottom Layer w15.75: v9(2149.61,991.65) 2154.4,978.6 v8(2165.35,948.82) 2187.99,930.61 2193.31,920.87 v8(2214.57,881.89)
  Bottom Layer w21.65: RAD_C26.2@614.12,1772.02 v3(649.61,1772.02) ; RAD_C23.2@614.12,1861.12 v3(649.61,1861.12)
  other v1: 1760.24,1298.23 1780.91,1298.23 1801.58,1298.23 1822.25,1298.23 1842.92,1298.23 1863.59,1298.23 1884.26,1298.23 1904.93,1298.23 1925.6,1298.23 1946.27,1298.23 1966.94,1298.23 1987.61,1298.23 2008.28,1298.23 2028.95,1298.23 2049.62,1298.23 2070.29,1298.23 2090.96,1298.23 2111.63,1298.23 2132.3,1298.23 2152.97,1298.23 2173.64,1298.23 2194.31,1298.23 2214.98,1298.23 2235.65,1298.23 2256.32,1298.23 2276.99,1298.23 2297.66,1298.23 2318.33,1298.23 2339,1298.38 2359.62,1299.73 2379,1302.66 2400.09,1308.07 2438.43,1323.23 1772.7,1328.91 1793.37,1328.91 1814.04,1328.91 1834.71,1328.91 1855.38,1328.91 1876.05,1328.91 1896.72,1328.91 1917.39,1328.91 1938.06,1328.91 1958.73,1328.91 1979.4,1328.91 2000.07,1328.91 2020.74,1328.91 2041.41,1328.91 2062.08,1328.91 2082.75,1328.91 2103.42,1328.91 2124.09,1328.91 2144.76,1328.91 2165.43,1328.91 2186.1,1328.91 2206.77,1328.91 2227.44,1328.91 2248.11,1328.91 2268.78,1328.91 2289.45,1328.91 2310.12,1328.91 2330.79,1328.91 2351.45,1329.74 2371.91,1332.63 2455.69,1332.7 2411.5,1344.36 2473.41,1345.4 1764.76,1349.41 1785.43,1349.41 1806.1,1349.41 1826.77,1349.41 1847.44,1349.41 1868.11,1349.41 1888.78,1349.41 1909.45,1349.41 1930.12,1349.41 1950.79,1349.41 1971.46,1349.41 1992.13,1349.41 2012.8,1349.41 2033.47,1349.41 2054.14,1349.41 2074.81,1349.41 2095.48,1349.41 2116.15,1349.41 2136.82,1349.41 2157.49,1349.41 2178.16,1349.41 2198.83,1349.41 2219.5,1349.41 2240.17,1349.41 2260.84,1349.41 2281.51,1349.41 2302.18,1349.41 2322.85,1349.41 2345.71,1349.81 2430.04,1353.5 2365.56,1354.36 2487.89,1357.48 2383.56,1362.57 2447.48,1364.6 2502.65,1371.87 2399.72,1374.56 2463.74,1377.36 1767.62,1380.09 1788.29,1380.09 1808.96,1380.09 1829.63,1380.09 1850.3,1380.09 1870.97,1380.09 1891.64,1380.09 1912.31,1380.09 1932.98,1380.09 1953.65,1380.09 1974.32,1380.09 1994.99,1380.09 2015.66,1380.09 2036.33,1380.09 2057,1380.09 2077.67,1380.09 2098.34,1380.09 2119.01,1380.09 2139.68,1380.09 2160.35,1380.09 2181.02,1380.09 2201.69,1380.09 2222.36,1380.09 2243.03,1380.09 2263.7,1380.09 2284.37,1380.09 2305.04,1380.09 2325.71,1380.09 2346.31,1381.9 2365.56,1389.42 2412.9,1389.51 2516.82,1389.51 2478.66,1391.67 1764.95,1400.59 1785.62,1400.59 1806.29,1400.59 1826.96,1400.59 1847.63,1400.59 1868.3,1400.59 1888.97,1400.59 1909.64,1400.59 1930.31,1400.59 1950.98,1400.59 1971.65,1400.59 1992.32,1400.59 2012.99,1400.59 2033.66,1400.59 2054.33,1400.59 2075,1400.59 2095.67,1400.59 2116.34,1400.59 2137.01,1400.59 2157.68,1400.59 2178.35,1400.59 2199.02,1400.59 2219.69,1400.59 2240.22,1402.13 2382.28,1401.57 2492.09,1407.37 2528.3,1406.7 2260.27,1407.54 2423.95,1408.82 2278.2,1415.68 2394.44,1418.28 2503.58,1424.56 2539.06,1425.63 2294.34,1427 2431.02,1428.24 1767.44,1431.27 1788.11,1431.27 1808.78,1431.27 1829.45,1431.27 1850.12,1431.27 1870.79,1431.27 1891.46,1431.27 1912.13,1431.27 1932.8,1431.27 1953.47,1431.27 1974.14,1431.27 1994.81,1431.27 2015.48,1431.27 2036.15,1431.27 2056.82,1431.27 2077.49,1431.27 2098.16,1431.27 2118.83,1431.27 2139.5,1431.27 2160.17,1431.27 2180.84,1431.27 2201.51,1431.27 2222.18,1431.18 2242.4,1434.57 2401.98,1437.53 2309.37,1441.25 2261.74,1442.51 2513.09,1442.91 2546.69,1443.69 2434.12,1448.68 1756.68,1451.78 1777.35,1451.78 1798.02,1451.78 1818.69,1451.78 2278.25,1454.41 2403.81,1458.12 2248.48,1460.21 2321.56,1460.89 2520.75,1462.11 2553.33,1463.27 2434.49,1469.34 2291.54,1470.21 2403.81,1478.79 2329.8,1479.84 1776.67,1482.45 1797.34,1482.45 1818.01,1482.45 2526.47,1481.97 2558.24,1482.98 2300.47,1488.85 2434.49,1490.01 2403.81,1499.46 2334.41,1499.99 2530.22,1502.3 2560.87,1503.89 2304.57,1509.11 2434.49,1510.68 2403.81,1520.13 2335.64,1520.63 2531.57,1522.93 2562.22,1524.51 2304.96,1529.78 2434.49,1531.35 2335.64,1541.3 2403.81,1540.8 2531.49,1543.6 2562.16,1545.18 2304.96,1550.45 2434.49,1552.02 2403.81,1561.47 2335.64,1561.97 2531.49,1564.27 2562.16,1565.85 2088.07,1569.29 2304.96,1571.12 2434.49,1572.69 2403.81,1582.14 2335.64,1582.64 1505.27,1584.43 1595.96,1584.43 2531.49,1584.94 2562.16,1586.52 1537.02,1588.67 1564.21,1588.67 2304.96,1591.79 2434.49,1593.36 1495.95,1598.71 1605.28,1598.71 2335.64,1603.31 2403.81,1602.81 2531.49,1605.61 1528.96,1607.5 1572.27,1607.5 2562.16,1607.19 2304.96,1612.46 2434.49,1614.03 1483.69,1618.42 1617.55,1618.42 2403.81,1623.48 1517.16,1624.22 1584.08,1624.22 2335.64,1623.98 2531.49,1626.28 2562.16,1627.86 1620.62,1632.98 2305.08,1633.13 2434.49,1634.7 1480.61,1635.81 1511.76,1638.83 1589.48,1638.83 2403.81,1644.15 2334.72,1644.55 2531.49,1646.95 2562.16,1648.53 2301.61,1653.5 1480.61,1655.46 1511.29,1655.46 1589.95,1655.46 1620.62,1655.46 2434.49,1655.37 2245.04,1658.29 2330.87,1664.12 2403.81,1664.82 2531.49,1667.62 2562.16,1669.2 2292.97,1672.28 1480.61,1676.13 1511.29,1676.13 1589.95,1676.13 1620.62,1676.13 2434.49,1676.04 2322.33,1683.47 2403.81,1685.49 2278.55,1687.28 2531.49,1688.29 2562.16,1689.87 1480.61,1696.8 1511.29,1696.8 1589.95,1696.8 1620.62,1696.8 2434.49,1696.71 2261.23,1697.97 2309.37,1700.34 2241,1702.67 2178.35,1703.67 2199.86,1703.67 2220.53,1703.67 2158.11,1706.16 2403.81,1706.16 2531.49,1708.96 2562.16,1710.54 2140.12,1712.27 2294.34,1714.52 1480.61,1717.47 1511.29,1717.47 1589.95,1717.47 1620.62,1717.47 2434.12,1717.46 2121.71,1721.9 2276.67,1725 2400.91,1726.62 2531.49,1729.63 2562.16,1731.21 2256.97,1731.84 2194.95,1734.34 2215.62,1734.34 2236.29,1734.24 2104.14,1735.44 2174.29,1735.04 1521.71,1735.97 1579.53,1735.97 2429.45,1737.58 1483.69,1739.6 1617.55,1739.6 2154.51,1740.1 2390.36,1744.39 2135.99,1749.41 2531.49,1750.3 2090.6,1751 2562.16,1751.88 1529.26,1756.34 1571.98,1756.34 2373.59,1756.48 2420.19,1756.06 1453.75,1758.81 1495.95,1758.81 1605.28,1758.81 1647.48,1758.81 2291.54,1761.07 2312.06,1760.84 2332.73,1760.84 2353.4,1760.9 2120.86,1763.48 2271.41,1767.02 2080.02,1768.88 2531.49,1770.97 2404.8,1773.02 2562.16,1772.55 1497.88,1779.48 1528.56,1779.48 1572.68,1779.48 1603.36,1779.48 2250.23,1779.72 2109.22,1780.52 2388.94,1783.42 2072.69,1787.96 2369.58,1789.73 2307.65,1791.52 2328.32,1791.52 2348.99,1791.52 2531.49,1791.64 2562.16,1793.22 2287.12,1793.89 2233.77,1799.27 1497.88,1800.15 1528.56,1800.15 1572.68,1800.15 1603.36,1800.15 2101.73,1799.58
  other v2: 1320.3,1313.57
  other v4: 1729.75,1287.99 1744.37,1294.88 1712.04,1298.21 1706.32,1314.04 1712.04,1328.92 1747.47,1328.91 1729.75,1339.17 1712.04,1349.39 1747.47,1349.41 1706.09,1364.91 1747.47,1380.09 1712.04,1381.9 1729.75,1390.35 1712.04,1400.57 1747.47,1400.59 1706.09,1416.13 1747.47,1431.27 1712.04,1433.8 1729.75,1441.53 1743.37,1447.38 1712.04,1451.75 1525.03,1467.11 1576.21,1467.11 1704.16,1467.11 1473.85,1469 1627.51,1469 1458.5,1474.99 1489.21,1474.99 1509.68,1474.99 1540.39,1474.99 1560.86,1474.99 1591.57,1474.99 1612.04,1474.99 1642.75,1474.99 1712.04,1482.46 1448.26,1492.7 1499.43,1492.7 1550.61,1492.7 1601.79,1492.7 1652.97,1492.7 1458.51,1510.42 1489.19,1510.42 1509.69,1510.42 1540.37,1510.42 1560.87,1510.42 1591.55,1510.42 1612.05,1510.42 1642.73,1510.42 1458.51,1528.81 1489.19,1528.81 1509.69,1528.81 1540.37,1528.81 1560.87,1528.81 1591.55,1528.81 1612.05,1528.81 1642.73,1528.81 1458.51,1546.48 1489.19,1546.48 1509.69,1546.48 1540.37,1546.48 1560.87,1546.48 1591.55,1546.48 1612.05,1546.48 1642.73,1546.48 1458.51,1565.15 1489.19,1565.15 1509.69,1565.15 1540.37,1565.15 1560.87,1565.15 1591.55,1565.15 1612.05,1565.15 1642.73,1565.15 1456.32,1583.87 1489.39,1583.78 1611.85,1583.78 1644.92,1583.87 1442.47,1598.71 1658.77,1598.71 1481.13,1603.5 1620.1,1603.5 1671.49,1615 1467.45,1617.7 1633.3,1618.42 1423.08,1634.73 1456.53,1634.79 1644.71,1634.79 1678.17,1634.73 1423.08,1655.46 1453.75,1655.46 1647.48,1655.46 1678.16,1655.46 1423.08,1676.13 1453.75,1676.13 1647.48,1676.13 1678.16,1676.13 1423.08,1696.8 1453.75,1696.8 1647.48,1696.8 1678.16,1696.8 1423.08,1717.47 1453.75,1717.47 1647.48,1717.47 1678.16,1717.47 1423.08,1738.14 1453.75,1738.14 1647.48,1738.14 1678.16,1738.14 1423.08,1758.81 1678.16,1758.81 1423.08,1779.48 1453.75,1779.48 1647.48,1779.48 1678.16,1779.48 1423.08,1800.15 1453.75,1800.15 1647.48,1800.15 1678.16,1800.15
  other v5: 1839.36,1451.78 1860.03,1451.78 1880.7,1451.78 1901.37,1451.78 1922.04,1451.78 1942.71,1451.78 2126.73,1452.11 2147.4,1452.11 2168.07,1452.11 2188.74,1452.11 2209.41,1452.11 2230.07,1451.58 1963.15,1454.3 2106.13,1453.76 2087.7,1461.46 1980.35,1466.44 2073.32,1477.76 2261.9,1477.87 1838.68,1482.45 1859.35,1482.45 1880.02,1482.45 1900.69,1482.45 1921.36,1482.45 1942.03,1482.45 2123.72,1482.78 2144.39,1482.78 2165.06,1482.78 2185.73,1482.78 2206.4,1482.78 2227.06,1483.33 1990.48,1484.46 2103.88,1488.59 1960.72,1491.29 2065.42,1497.25 2263.46,1498.66 2232.79,1503.19 1992.42,1505.04 2096.1,1507.74 1961.74,1511.93 2065.42,1517.89 2263.46,1519.34 2232.79,1523.86 1992.42,1525.71 2096.1,1528.41 1961.74,1532.6 2065.42,1538.56 2263.46,1540.01 2232.79,1544.53 1992.99,1546.37 2095.67,1549.33 1963.15,1553.22 2011.71,1555.12 2032.38,1555.12 2053.05,1555.12 2263.46,1560.67 2232.79,1565.2 1972.82,1571.49 2263.46,1581.35 2072.22,1581.87 1990.48,1583.43 2010.48,1585.8 2031.15,1585.8 2051.82,1585.8 2232.79,1585.87 2263.46,1602.02 2232.79,1606.54 2263.26,1622.68 2231.37,1627.16 2129.85,1635.98 2150.52,1635.66 2171.19,1635.66 2191.86,1635.66 2212.53,1635.66 2109.23,1637.34 2090.96,1640.28 2257.74,1642.6 2069.2,1645.53 2049.5,1653.53 2030.96,1662.67 2162.62,1666.34 2183.29,1666.34 2203.96,1666.34 2224.28,1665.99 2121.62,1667.37 2141.66,1666.62 2101.13,1670.23 2012.8,1673.06 2080.9,1675.04 2061.53,1682.03 1996.63,1685.65 2042.9,1691.19 1981.09,1699.28 2025.63,1702.26 1965.66,1715.09 2009.48,1715.24 1994.85,1729.7 1953.36,1731.84 1981.71,1745.71 1943.34,1748.32 1970.3,1762.96 1934.2,1766.85 1961.21,1781.7 1926.03,1785.47 1954.28,1801.21
  other v11: 1564.4,1441.52 1633.29,1441.52 1661.42,1445.87 1385.26,1467.11
  other v13: 2126.57,1239.86 1996.06,1750.39
  other v16: 2322.83,1594.49
  other v21: 748.03,1791.34 826.77,1791.34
